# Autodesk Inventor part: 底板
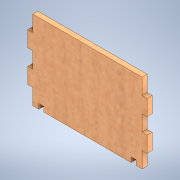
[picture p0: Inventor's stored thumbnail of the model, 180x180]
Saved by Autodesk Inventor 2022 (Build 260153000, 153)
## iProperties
Created: 2024-11
Part Number: 底板
Material: MDF 中密度繊維ボード
Document SubType Name: Modeling
Designer: shimizu
Density: 0.8 g/cm^3
Appearance: サクラ材 - ナチュラル 抑えた光沢
Author: shimizu
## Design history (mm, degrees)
sketch "スケッチ1"
  geometry: L1 (-25.119, 10.226)-(29.881, 10.226); L2 (29.881, -29.774)-(-25.119, -29.774); L3 (-25.119, 2.226)-(-27.619, 2.226); L4 (-27.619, 2.226)-(-27.619, -5.774); L5 (-27.619, -5.774)-(-25.119, -5.774); L6 (-25.119, -13.774)-(-27.619, -13.774); L7 (-27.619, -13.774)-(-27.619, -21.774); L8 (-27.619, -21.774)-(-25.119, -21.774); L9 (29.881, 2.226)-(32.381, 2.226); L10 (32.381, 2.226)-(32.381, -5.774); L11 (32.381, -5.774)-(29.881, -5.774); L12 (29.881, -13.774)-(32.381, -13.774); L13 (32.381, -13.774)-(32.381, -21.774); L14 (32.381, -21.774)-(29.881, -21.774); L15 (-25.119, 2.226)-(-25.119, 10.226); L16 (-25.119, -29.774)-(-25.119, -21.774); L17 (-25.119, -13.774)-(-25.119, -5.774); L18 (29.881, 10.226)-(29.881, 2.226); L19 (29.881, -5.774)-(29.881, -13.774); L20 (29.881, -21.774)-(29.881, -29.774); L21 (-22.119, -29.774)-(-19.619, -29.774); L22 (-19.619, -29.774)-(-19.619, -27.274); L23 (-19.619, -27.274)-(-22.119, -27.274); L24 (-22.119, -27.274)-(-22.119, -29.774); L25 (24.381, -27.274)-(26.881, -27.274); L26 (26.881, -27.274)-(26.881, -29.774); L27 (26.881, -29.774)-(24.381, -29.774); L28 (24.381, -29.774)-(24.381, -27.274); 3 further points
  constraints: 56 end point, 20 parallel, 9 perpendicular, 7 horizontal, 4 collinear, 2 point on line
  dimensions: "d16" = 60 distance between parallel lines of L13 L7; "d17" = 2.5 distance between parallel lines of L22 L24; "d18" = 2.5 distance between parallel lines of L2 L23; "d19" = 3 distance between parallel lines of L16 L24; "d20" = 2.5 distance of L25.start L25.end; "d21" = 2.5 distance of L25.end L26.end; "d22" = 3 distance between parallel lines of L20 L26; "d23" = 2.5 distance of L9.start L9.end; "d24" = 2.5 distance of L3.start L3.end
extrude "押し出し1" new body sketch "スケッチ1" distance "d2" = 2.5; taper "d3" = 0 deg
node "ソリッド1"
